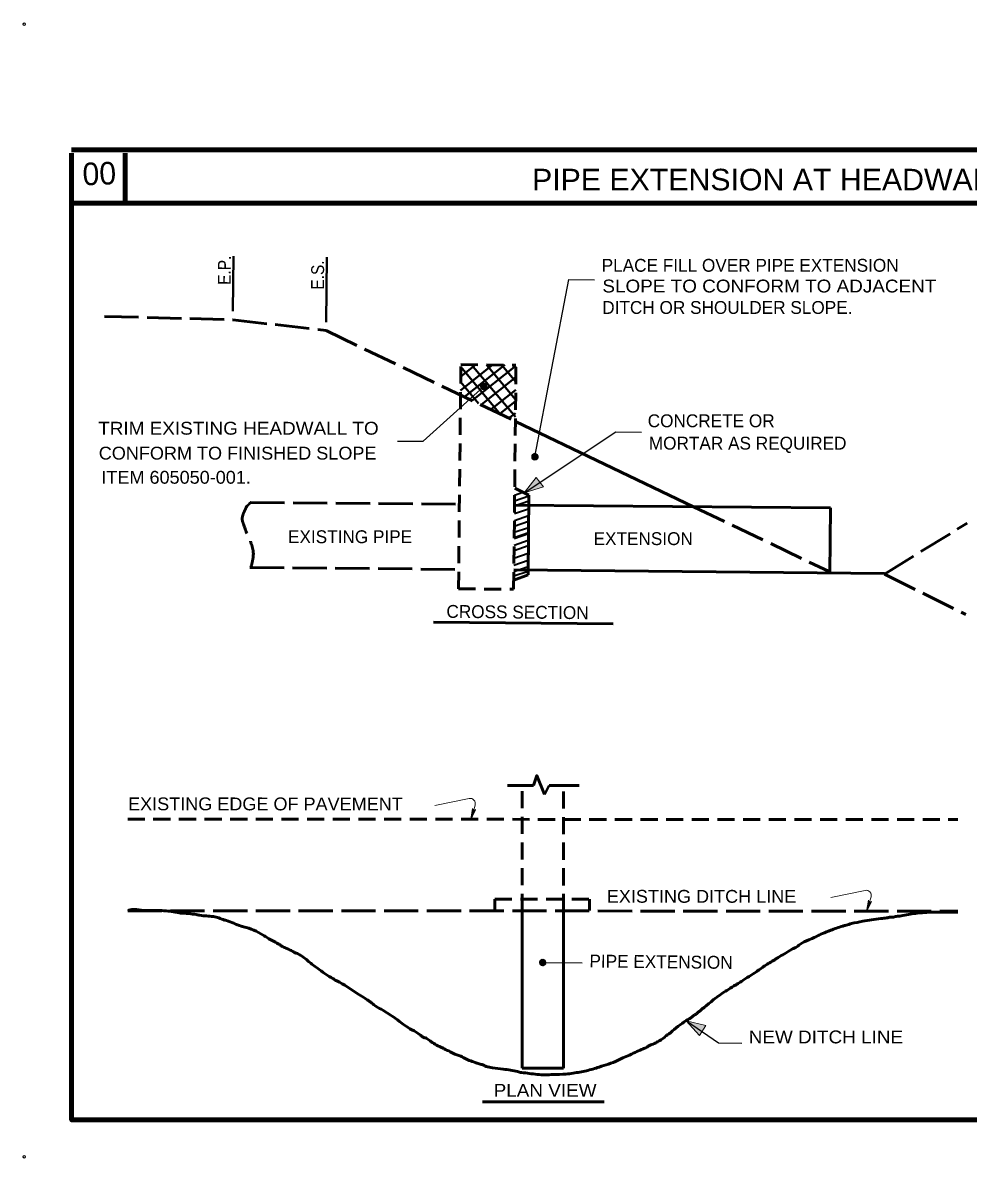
# Model space of a CAD drawing. Extents: x -8731 to 7714, y -62866 to -56618.
# Drawn here: x 6119 to 7114, y -62866 to -61670 of the extents above; entities that cross this region are included whole.
import ezdxf
from ezdxf.enums import TextEntityAlignment as Align

# ---------------------------------------------------------------- set-up
doc = ezdxf.new("R2010")
doc.units = 0
doc.header["$LTSCALE"] = 6
doc.header["$PDMODE"] = 32
doc.header["$PDSIZE"] = 3
doc.linetypes.add('LONG_DASHED', pattern=[7.5, 6, -1.5])
doc.linetypes.add('MEDIUM_DASHED', pattern=[4.5, 3, -1.5])
doc.layers.add('1', color=7, linetype='Continuous', lineweight=13)
doc.layers.add('3', color=7, linetype='Continuous', lineweight=53)

msp = doc.modelspace()

# ---------------------------------------------------------------- hatches: boundary and pattern name
at = {"layer": '1'}
for points in [[(6646.72, -62165.12), (6666.94, -62158.84), (6659.54, -62148.78)], [(6817.38, -62721.06), (6837.94, -62725.98), (6831.24, -62736.52)]]:
    msp.add_hatch(color=256, dxfattribs=at).paths.add_polyline_path(points)

# ---------------------------------------------------------------- linework, layer by layer
at = {"layer": '1', "lineweight": 100}
for p, q in [((7662.46, -61803.8), (6170.24, -61803.8)), ((6226.5, -61807.3), (6226.5, -61860.06)), ((7662.46, -61860.06), (6170.24, -61860.06)), ((7662.46, -62825.24), (7022.34, -62825.24))]:
    msp.add_line(p, q, dxfattribs=at)
at = {"layer": '1'}
for p, q in [((6600.9, -62053.06), (6604.24, -62049.72)), ((6600.9, -62052.62), (6603.8, -62049.72)), ((6600.9, -62053.5), (6604.54, -62049.72)), ((6600.9, -62053.78), (6604.98, -62049.72)), ((6600.9, -62054.22), (6605.4, -62049.86)), ((6601.04, -62052.04), (6603.08, -62049.86)), ((6601.18, -62054.36), (6605.54, -62050)), ((6601.34, -62054.8), (6605.84, -62050.16)), ((6601.48, -62055.1), (6606.28, -62050.3)), ((6601.62, -62055.38), (6606.42, -62050.58)), ((6601.78, -62055.68), (6606.72, -62050.72)), ((6602.2, -62055.82), (6607, -62051.02)), ((6602.34, -62056.12), (6607.14, -62051.16)), ((6602.64, -62056.26), (6607.3, -62051.6)), ((6603.08, -62056.26), (6607.58, -62051.9)), ((6603.5, -62056.4), (6607.58, -62052.18)), ((6603.8, -62056.56), (6607.58, -62052.62)), ((6604.1, -62056.56), (6607.74, -62052.92)), ((6604.54, -62056.56), (6607.58, -62053.5)), ((6604.98, -62056.56), (6607.58, -62053.92)), ((6605.4, -62056.4), (6607.58, -62054.36)), ((6654.74, -62126.96), (6658.08, -62123.62)), ((6654.74, -62126.54), (6657.64, -62123.62)), ((6654.74, -62127.4), (6658.36, -62123.62)), ((6654.74, -62127.7), (6658.8, -62123.62)), ((6654.74, -62128.14), (6659.24, -62123.76)), ((6654.88, -62125.96), (6656.9, -62123.76)), ((6655.02, -62128.28), (6659.38, -62123.92)), ((6655.16, -62128.72), (6659.68, -62124.06)), ((6655.3, -62129), (6660.1, -62124.2)), ((6655.46, -62129.3), (6660.26, -62124.5)), ((6655.6, -62129.6), (6660.54, -62124.64)), ((6656.04, -62129.74), (6660.84, -62124.94)), ((6656.18, -62130.04), (6660.98, -62125.08)), ((6656.48, -62130.18), (6661.14, -62125.52)), ((6656.9, -62130.18), (6661.42, -62125.8)), ((6657.34, -62130.32), (6661.42, -62126.1)), ((6657.64, -62130.46), (6661.42, -62126.54)), ((6657.94, -62130.46), (6661.58, -62126.82)), ((6658.36, -62130.46), (6661.42, -62127.4)), ((6658.8, -62130.46), (6661.42, -62127.84)), ((6659.24, -62130.32), (6661.42, -62128.28)), ((6552.74, -62494.22), (6588.82, -62486.94)), ((6590.42, -62509.2), (6595.22, -62493.78)), ((6592.3, -62497.28), (6590.42, -62509.2)), ((6592.3, -62497.42), (6590.42, -62509.06)), ((6590.42, -62509.2), (6595.66, -62498.58)), ((6590.42, -62509.06), (6595.66, -62498.58)), ((6592.3, -62497.42), (6590.56, -62508.76)), ((6592.3, -62497.7), (6590.56, -62508.32)), ((6590.56, -62508.76), (6595.66, -62498.72)), ((6590.56, -62508.32), (6595.36, -62498.72)), ((6592.3, -62497.7), (6590.86, -62508.18)), ((6592.3, -62497.7), (6590.86, -62508.18)), ((6592.3, -62497.84), (6590.86, -62507.74)), ((6592.3, -62497.84), (6590.86, -62507.88)), ((6590.86, -62508.18), (6595.36, -62498.72)), ((6590.86, -62507.88), (6595.36, -62499.02)), ((6590.86, -62507.74), (6595.22, -62499.02)), ((6592.3, -62498.14), (6591, -62507.32)), ((6592.6, -62498.14), (6591, -62507.02)), ((6591, -62507.32), (6595.22, -62499.02)), ((6591, -62507.02), (6594.94, -62499.02)), ((6592.6, -62498.28), (6591.3, -62506.88)), ((6592.6, -62498.28), (6591.3, -62506.44)), ((6592.6, -62498.58), (6591.3, -62506.14)), ((6591.3, -62506.88), (6594.94, -62499.16)), ((6591.3, -62506.44), (6594.94, -62499.16)), ((6591.3, -62506.14), (6594.78, -62499.16)), ((6592.6, -62498.58), (6591.44, -62506)), ((6592.6, -62498.72), (6591.44, -62505.72)), ((6592.6, -62498.72), (6591.44, -62505.28)), ((6591.44, -62506), (6594.78, -62499.44)), ((6591.44, -62505.72), (6594.5, -62499.44)), ((6591.44, -62505.28), (6594.5, -62499.44)), ((6592.6, -62499.02), (6591.74, -62505.12)), ((6592.74, -62499.02), (6591.74, -62504.68)), ((6592.6, -62499.02), (6591.74, -62504.68)), ((6591.74, -62505.12), (6594.5, -62499.6)), ((6591.74, -62504.68), (6594.34, -62499.6)), ((6592.74, -62499.16), (6591.86, -62504.4)), ((6592.74, -62499.16), (6591.86, -62504.26)), ((6592.74, -62499.44), (6591.86, -62503.96)), ((6591.86, -62504.4), (6594.34, -62499.6)), ((6591.86, -62504.26), (6594.06, -62499.6)), ((6591.86, -62503.96), (6594.06, -62499.88)), ((6592.74, -62499.44), (6592.16, -62503.82)), ((6592.74, -62499.6), (6592.16, -62503.38)), ((6592.16, -62503.82), (6594.06, -62499.88)), ((6592.16, -62503.38), (6593.9, -62499.88)), ((6593.04, -62500.48), (6592.3, -62497.28)), ((6592.74, -62499.6), (6592.3, -62503.08)), ((6592.74, -62499.88), (6592.3, -62502.94)), ((6592.74, -62499.88), (6592.3, -62502.52)), ((6592.3, -62503.08), (6593.9, -62500.04)), ((6592.3, -62502.94), (6593.62, -62500.04)), ((6592.3, -62502.52), (6593.62, -62500.04)), ((6593.04, -62499.88), (6592.6, -62502.22)), ((6592.6, -62502.22), (6593.62, -62500.04)), ((6593.04, -62500.04), (6592.6, -62502.08)), ((6592.6, -62502.08), (6593.48, -62500.32)), ((6593.04, -62500.04), (6592.74, -62501.78)), ((6592.74, -62501.78), (6593.48, -62500.32)), ((6592.74, -62501.34), (6593.18, -62500.32)), ((6593.04, -62500.32), (6592.74, -62501.34)), ((6592.74, -62501.2), (6593.18, -62500.48)), ((6595.66, -62498.58), (6593.04, -62500.48)), ((6593.04, -62500.92), (6593.18, -62500.48)), ((6593.04, -62500.48), (6593.04, -62500.92)), ((6593.04, -62500.48), (6593.04, -62500.92)), ((6969.58, -62590.96), (7005.68, -62583.7)), ((7007.28, -62605.96), (7012.08, -62590.54)), ((7009.18, -62594.04), (7007.28, -62605.96)), ((7009.18, -62594.16), (7007.28, -62605.8)), ((7007.28, -62605.96), (7012.52, -62595.34)), ((7007.28, -62605.8), (7012.52, -62595.34)), ((7009.18, -62594.16), (7007.42, -62605.52)), ((7009.18, -62594.46), (7007.42, -62605.08)), ((7007.42, -62605.52), (7012.52, -62595.48)), ((7007.42, -62605.08), (7012.22, -62595.48)), ((7009.18, -62594.46), (7007.7, -62604.94)), ((7009.18, -62594.46), (7007.7, -62604.94)), ((7009.18, -62594.6), (7007.7, -62604.5)), ((7009.18, -62594.6), (7007.7, -62604.64)), ((7007.7, -62604.94), (7012.22, -62595.48)), ((7007.7, -62604.64), (7012.22, -62595.78)), ((7007.7, -62604.5), (7012.08, -62595.78)), ((7009.18, -62594.9), (7007.86, -62604.06)), ((7009.46, -62594.9), (7007.86, -62603.78)), ((7007.86, -62604.06), (7012.08, -62595.78)), ((7007.86, -62603.78), (7011.78, -62595.78)), ((7009.46, -62595.04), (7008.14, -62603.64)), ((7009.46, -62595.04), (7008.14, -62603.2)), ((7009.46, -62595.34), (7008.14, -62602.9)), ((7008.14, -62603.64), (7011.78, -62595.92)), ((7008.14, -62603.2), (7011.78, -62595.92)), ((7008.14, -62602.9), (7011.64, -62595.92)), ((7009.46, -62595.34), (7008.3, -62602.76)), ((7009.46, -62595.48), (7008.3, -62602.46)), ((7009.46, -62595.48), (7008.3, -62602.04)), ((7008.3, -62602.76), (7011.64, -62596.2)), ((7008.3, -62602.46), (7011.34, -62596.2)), ((7008.3, -62602.04), (7011.34, -62596.2)), ((7009.46, -62595.78), (7008.58, -62601.88)), ((7009.6, -62595.78), (7008.58, -62601.44)), ((7009.46, -62595.78), (7008.58, -62601.44)), ((7008.58, -62601.88), (7011.34, -62596.36)), ((7008.58, -62601.44), (7011.2, -62596.36)), ((7009.6, -62595.92), (7008.74, -62601.16)), ((7009.6, -62595.92), (7008.74, -62601)), ((7009.6, -62596.2), (7008.74, -62600.72)), ((7008.74, -62601.16), (7011.2, -62596.36)), ((7008.74, -62601), (7010.9, -62596.36)), ((7008.74, -62600.72), (7010.9, -62596.64)), ((7009.6, -62596.2), (7009.02, -62600.58)), ((7009.6, -62596.36), (7009.02, -62600.14)), ((7009.02, -62600.58), (7010.9, -62596.64)), ((7009.02, -62600.14), (7010.78, -62596.64)), ((7009.9, -62597.24), (7009.18, -62594.04)), ((7009.6, -62596.36), (7009.18, -62599.84)), ((7009.6, -62596.64), (7009.18, -62599.7)), ((7009.6, -62596.64), (7009.18, -62599.26)), ((7009.18, -62599.84), (7010.78, -62596.8)), ((7009.18, -62599.7), (7010.48, -62596.8)), ((7009.18, -62599.26), (7010.48, -62596.8)), ((7009.9, -62596.64), (7009.46, -62598.98)), ((7009.46, -62598.98), (7010.48, -62596.8)), ((7009.9, -62596.8), (7009.46, -62598.84)), ((7009.46, -62598.84), (7010.34, -62597.08)), ((7009.9, -62596.8), (7009.6, -62598.54)), ((7009.6, -62598.54), (7010.34, -62597.08)), ((7009.6, -62598.1), (7010.04, -62597.08)), ((7009.9, -62597.08), (7009.6, -62598.1)), ((7009.6, -62597.96), (7010.04, -62597.24)), ((7012.52, -62595.34), (7009.9, -62597.24)), ((7009.9, -62597.66), (7010.04, -62597.24)), ((7009.9, -62597.24), (7009.9, -62597.66)), ((7009.9, -62597.24), (7009.9, -62597.66)), ((6662.88, -62659.5), (6666.22, -62656.16)), ((6662.88, -62659.06), (6665.78, -62656.16)), ((6662.88, -62659.94), (6666.52, -62656.16)), ((6662.88, -62660.24), (6666.94, -62656.16)), ((6662.88, -62660.66), (6667.38, -62656.3)), ((6663.02, -62658.48), (6665.06, -62656.3)), ((6663.18, -62660.8), (6667.54, -62656.44)), ((6663.32, -62661.24), (6667.82, -62656.6)), ((6663.46, -62661.54), (6668.26, -62656.74)), ((6663.6, -62661.84), (6668.4, -62657.04)), ((6663.74, -62662.12), (6668.7, -62657.18)), ((6664.18, -62662.26), (6668.98, -62657.46)), ((6664.34, -62662.56), (6669.14, -62657.6)), ((6664.62, -62662.7), (6669.28, -62658.04)), ((6665.06, -62662.7), (6669.58, -62658.34)), ((6665.5, -62662.84), (6669.58, -62658.64)), ((6665.78, -62663), (6669.58, -62659.06)), ((6666.08, -62663), (6669.72, -62659.36)), ((6666.52, -62663), (6669.58, -62659.94)), ((6666.94, -62663), (6669.58, -62660.38)), ((6667.38, -62662.84), (6669.58, -62660.8))]:
    msp.add_line(p, q, dxfattribs=at)
at = {"layer": '1', "lineweight": 100}
msp.add_lwpolyline([(6170.24, -61807.3), (6170.24, -62825.24), (7661, -62825.24)], dxfattribs=at)
at = {"layer": '1'}
for points in [[(6646.72, -62165.12), (6666.94, -62158.84), (6659.54, -62148.78)], [(6817.38, -62721.06), (6837.94, -62725.98), (6831.24, -62736.52)]]:
    msp.add_lwpolyline(points, close=True, dxfattribs=at)
for points in [[(6593.04, -62500.76), (6593.04, -62500.48), (6590.42, -62509.2)], [(7009.9, -62597.52), (7009.9, -62597.24), (7007.28, -62605.96)]]:
    msp.add_lwpolyline(points, dxfattribs=at)
for centre in [(6604.24, -62053.2), (6658.07, -62127.12), (6666.22, -62659.65)]:
    msp.add_circle(centre, 3.42, dxfattribs=at)
for centre in [(6589.85, -62492.21), (7006.7, -62588.96)]:
    msp.add_arc(centre, 5.46, 342.9622, 101.31006, dxfattribs=at)
for p in [(6120.3, -61671.6), (6120.3, -62864.2)]:
    msp.add_point(p, dxfattribs=at)
at = {"layer": '3', "lineweight": 40}
for p, q in [((6340.16, -61973.76), (6340.74, -61916)), ((6438.38, -61985.26), (6438.94, -61917.02)), ((6579.8, -62057.28), (6613.54, -62030.36)), ((6579.94, -62042.58), (6595.36, -62030.22)), ((6580.1, -62032.54), (6621.56, -62082.16)), ((6583.86, -62063.96), (6626.36, -62030.22)), ((6591.44, -62030.22), (6637.56, -62085.22)), ((6592.02, -62067.9), (6638.14, -62031.38)), ((6607.14, -62030.36), (6637.7, -62066.88)), ((6623.16, -62030.5), (6638, -62048.12)), ((6579.94, -62048.7), (6598.7, -62071.1)), ((6601.78, -62072.12), (6638, -62043.32)), ((6611.8, -62077.36), (6637.86, -62056.7)), ((6621.12, -62081.88), (6637.7, -62068.62)), ((6630.58, -62086.52), (6637.56, -62081.14)), ((6668.26, -62482.72), (6672.92, -62473.12))]:
    msp.add_line(p, q, dxfattribs=at)
at = {"layer": '3', "lineweight": 25}
for p, q in [((6658.08, -62127.12), (6693.72, -61940.58)), ((6693.72, -61940.58), (6720.64, -61940.88)), ((6540.36, -62110.82), (6604.24, -62053.2)), ((6513.46, -62110.52), (6540.36, -62110.82)), ((6666.22, -62659.64), (6707.7, -62660.08))]:
    msp.add_line(p, q, dxfattribs=at)
at = {"layer": '3', "linetype": 'LONG_DASHED'}
for p, q in [((6438.22, -61994.28), (6637.56, -62089.88)), ((6358.5, -62175.12), (6578.5, -62177.16)), ((6825.1, -62179.64), (6967.98, -62248.04)), ((7026.18, -62250.64), (7113.06, -62196.96)), ((6357.9, -62243.66), (6577.76, -62245.7)), ((7026.18, -62250.64), (7111.9, -62293.28)), ((6229.3, -62605.08), (7103.16, -62605.52))]:
    msp.add_line(p, q, dxfattribs=at)
at = {"layer": '3', "linetype": 'MEDIUM_DASHED'}
for p, q in [((6577.62, -62266.08), (6580.1, -62030.08)), ((6580.1, -62030.08), (6638.14, -62030.64)), ((6635.66, -62266.64), (6638.14, -62030.64)), ((6577.62, -62266.08), (6635.66, -62266.64)), ((6644.54, -62605.24), (6644.54, -62473.12)), ((6688.06, -62605.38), (6688.06, -62473.12)), ((6229.3, -62508.62), (7103.16, -62509.06)), ((6615.88, -62604.94), (6615.88, -62592.86)), ((6615.88, -62592.86), (6715.4, -62592.86)), ((6715.4, -62604.94), (6715.4, -62592.86))]:
    msp.add_line(p, q, dxfattribs=at)
at = {"layer": '3'}
for p, q in [((6637.56, -62089.88), (6825.1, -62179.64)), ((6636.82, -62160.28), (6651.54, -62167.56)), ((6650.8, -62251.52), (6651.54, -62167.56)), ((6636.54, -62177.9), (6969.3, -62180.96)), ((6968.72, -62249.48), (6969.3, -62180.96)), ((6636.26, -62212.82), (6651.24, -62207.58)), ((6635.82, -62246.28), (7026.18, -62250.06)), ((6635.82, -62257.04), (6650.8, -62251.52)), ((6551.42, -62301.14), (6740.28, -62303.04)), ((6629.12, -62473.12), (6656.48, -62473.12)), ((6672.92, -62473.12), (6704.64, -62473.12)), ((6644.54, -62770.8), (6644.54, -62605.24)), ((6688.06, -62770.8), (6688.06, -62605.38)), ((6644.54, -62770.8), (6688.06, -62770.8)), ((6602.94, -62806.32), (6731.12, -62806.32))]:
    msp.add_line(p, q, dxfattribs=at)
at = {"layer": '3', "lineweight": 35}
for p, q in [((6636.7, -62167.56), (6645.42, -62164.52)), ((6636.7, -62173.38), (6651.54, -62168.16)), ((6636.54, -62178.62), (6651.54, -62173.38)), ((6636.54, -62186.92), (6651.38, -62181.82)), ((6636.1, -62200.3), (6651.24, -62195.06)), ((6636.4, -62194.34), (6651.38, -62189.1)), ((6636.26, -62206.56), (6651.24, -62201.48)), ((6636.1, -62220.08), (6651.1, -62214.86)), ((6635.96, -62233.76), (6650.94, -62228.52)), ((6636.1, -62225.92), (6651.1, -62220.68)), ((6635.82, -62247.88), (6650.94, -62242.64)), ((6635.96, -62241.2), (6650.94, -62235.96)), ((6635.82, -62252.54), (6650.8, -62247.44))]:
    msp.add_line(p, q, dxfattribs=at)
at = {"layer": '3', "linetype": 'LONG_DASHED'}
msp.add_lwpolyline([(6204.84, -61979.28), (6340.02, -61982.78), (6438.22, -61994.28)], dxfattribs=at)
at = {"layer": '3', "lineweight": 25}
for points in [[(6646.72, -62165.24), (6743.34, -62100.78), (6770.26, -62101.08)], [(6817.7, -62720.9), (6851.44, -62744.18), (6876.04, -62744.48)]]:
    msp.add_lwpolyline(points, dxfattribs=at)
at = {"layer": '3'}
msp.add_lwpolyline([(6656.48, -62473.12), (6659.98, -62462.78), (6668.26, -62482.72)], dxfattribs=at)
at = {"layer": '3', "linetype": 'LONG_DASHED'}
msp.add_spline([(6358.5, -62175.12), (6357.34, -62176.74), (6355.58, -62178.34), (6352.82, -62183.14), (6351.22, -62186.64), (6350.2, -62189.98), (6349.9, -62193.18), (6351.36, -62198.28), (6354.12, -62206.28), (6357.62, -62213.98), (6360.68, -62222.72), (6361.54, -62227.52), (6361.54, -62231.3), (6360.82, -62236.4), (6359.06, -62243.52)], degree=3, dxfattribs=at)
at = {"layer": '3'}
for points in [[(6229.3, -62605.08), (6232.06, -62604.2), (6235.26, -62603.78), (6238.74, -62603.78), (6241.22, -62604.2), (6258.82, -62604.8), (6263.04, -62604.8), (6271.92, -62605.52), (6279.2, -62606.4), (6281.82, -62606.98), (6293.9, -62608.14), (6301.46, -62609.16), (6305.1, -62609.88), (6319.5, -62611.2), (6325.32, -62612.64), (6331.42, -62614.84), (6333.18, -62615.28), (6348.9, -62621.38), (6351.36, -62621.96), (6371.88, -62630.7), (6376.68, -62633.76), (6387.88, -62639.86), (6391.08, -62641.9), (6395.88, -62644.52), (6403.3, -62647.86), (6404.9, -62648.88), (6407.96, -62650.2), (6412.32, -62652.66), (6417.56, -62656.44), (6422.08, -62660.38), (6427.02, -62664), (6443.62, -62675.36), (6445.64, -62676.52), (6447.68, -62678.12), (6449.42, -62679), (6470.96, -62692.1), (6477.8, -62696.46), (6487.54, -62703.16), (6489.44, -62704.76), (6496.14, -62708.82), (6515.62, -62721.78), (6520.86, -62725.7), (6528.44, -62730.36), (6537.46, -62736.04), (6540.5, -62738.22), (6543.42, -62739.24), (6547.64, -62742), (6558.98, -62748.7), (6562.34, -62750.3), (6564.08, -62751.32), (6565.98, -62752.04), (6571.66, -62755.1), (6579.94, -62758.16), (6583.14, -62759.9), (6595.08, -62764.84), (6599.44, -62766.3), (6603.38, -62767.46), (6606.72, -62768.92), (6613.54, -62770.38), (6624.76, -62771.84), (6639.74, -62774.44), (6641.92, -62775.04), (6643.96, -62775.32), (6660.26, -62777.36), (6668.98, -62777.8), (6677.42, -62777.5), (6690.66, -62777.06), (6698.24, -62776.04), (6712.2, -62773.58), (6725.74, -62769.64), (6735.62, -62766.44), (6745.08, -62762.8), (6750.62, -62760.04), (6757.6, -62757.12), (6765.46, -62753.2), (6772, -62750.44), (6773.74, -62749.72), (6775.94, -62748.7), (6778.84, -62746.96), (6783.64, -62744.92), (6787.14, -62743.02), (6794.42, -62738.36), (6796.16, -62736.76), (6797.76, -62735.74), (6802.86, -62731.68), (6819.58, -62719.44), (6822.5, -62717.56), (6825.4, -62715.24), (6827, -62714.36), (6829.48, -62712.18), (6832.24, -62710.14), (6834.42, -62708.1), (6836.02, -62707.22), (6837.48, -62705.76), (6840.1, -62703.74), (6844.6, -62699.96), (6851.16, -62695)], [(6851.16, -62695), (6857.7, -62690.5), (6860.02, -62689.18), (6867.46, -62684.24), (6870.8, -62682.48), (6875.46, -62679.44), (6891.74, -62668.96), (6901.2, -62662.26), (6911.82, -62655.86), (6914.16, -62654.26), (6920.86, -62650.48), (6928.26, -62645.82), (6930.46, -62644.8), (6934.82, -62642.2), (6936.86, -62640.6), (6946.46, -62635.78), (6960.86, -62629.08), (6969.44, -62625.6), (6982.1, -62621.24), (6985.74, -62620.22), (6991.42, -62618.62), (7003.2, -62616.14), (7012.52, -62614.54), (7022.12, -62613.38), (7024.02, -62613.08), (7029.54, -62612.36), (7031.28, -62611.92), (7034.62, -62611.78), (7038.56, -62611.04), (7043.5, -62610.48), (7051.36, -62609.02), (7066.2, -62607.12), (7103.16, -62606.68)]]:
    msp.add_spline(points, degree=3, dxfattribs=at)

# ---------------------------------------------------------------- texts
at = {"layer": '1'}
msp.add_text('00', height=23.78, rotation=2.121, dxfattribs=at).set_placement((6182.18, -61841.44))
at = {"layer": '3', "width": 1.05}
msp.add_text('PIPE EXTENSION AT HEADWALL ', height=22.7, dxfattribs=at).set_placement((6909.18, -61846.6), align=Align.CENTER)
at = {"layer": '3'}
for s, rotation, width, p in [('E.P.', 89.423, 0.9, (6337.74, -61946.16)), ('E.S.', 89.511, 0.9, (6435.92, -61951.16)), ('EXISTING EDGE OF PAVEMENT', 359.971, 1.05, (6229.72, -62499.3)), ('EXISTING DITCH LINE', 359.971, 1.05, (6733.74, -62596.64))]:
    msp.add_text(s, height=13.53, rotation=rotation, dxfattribs=dict(at, width=width)).set_placement(p)
for s, p in [('PLACE FILL OVER PIPE EXTENSION', (6728.34, -61932.3)), ('DITCH OR SHOULDER SLOPE.', (6728.94, -61976.68)), ('CONCRETE OR', (6776.8, -62095.98)), ('MORTAR AS REQUIRED', (6777.98, -62119.56))]:
    msp.add_text(s, height=13.53, dxfattribs=at).set_placement(p)
for s, width, p in [('SLOPE TO CONFORM TO ADJACENT', 1.1, (6729.08, -61954.12)), ('TRIM EXISTING HEADWALL TO', 1.1, (6198.3, -62103.84)), ('CONFORM TO FINISHED SLOPE', 1.05, (6198.88, -62130.04)), ('ITEM 605050-001.', 1.05, (6201.64, -62155.48)), ('NEW DITCH LINE', 1.1, (6883.16, -62744.7)), ('PLAN VIEW', 1.1, (6614.58, -62800.92))]:
    msp.add_text(s, height=13.53, dxfattribs=dict(at, width=width)).set_placement(p)
for s, p in [('EXISTING PIPE', (6463.45, -62218.06)), ('EXTENSION', (6772.07, -62220.08))]:
    msp.add_text(s, height=13.53, dxfattribs=at).set_placement(p, align=Align.CENTER)
for s, rotation, p in [('CROSS SECTION', 359.426, (6564.82, -62296.62)), ('PIPE EXTENSION', 359.397, (6715.4, -62664.74))]:
    msp.add_text(s, height=13.53, rotation=rotation, dxfattribs=at).set_placement(p)

doc.saveas('drawing.dxf')
